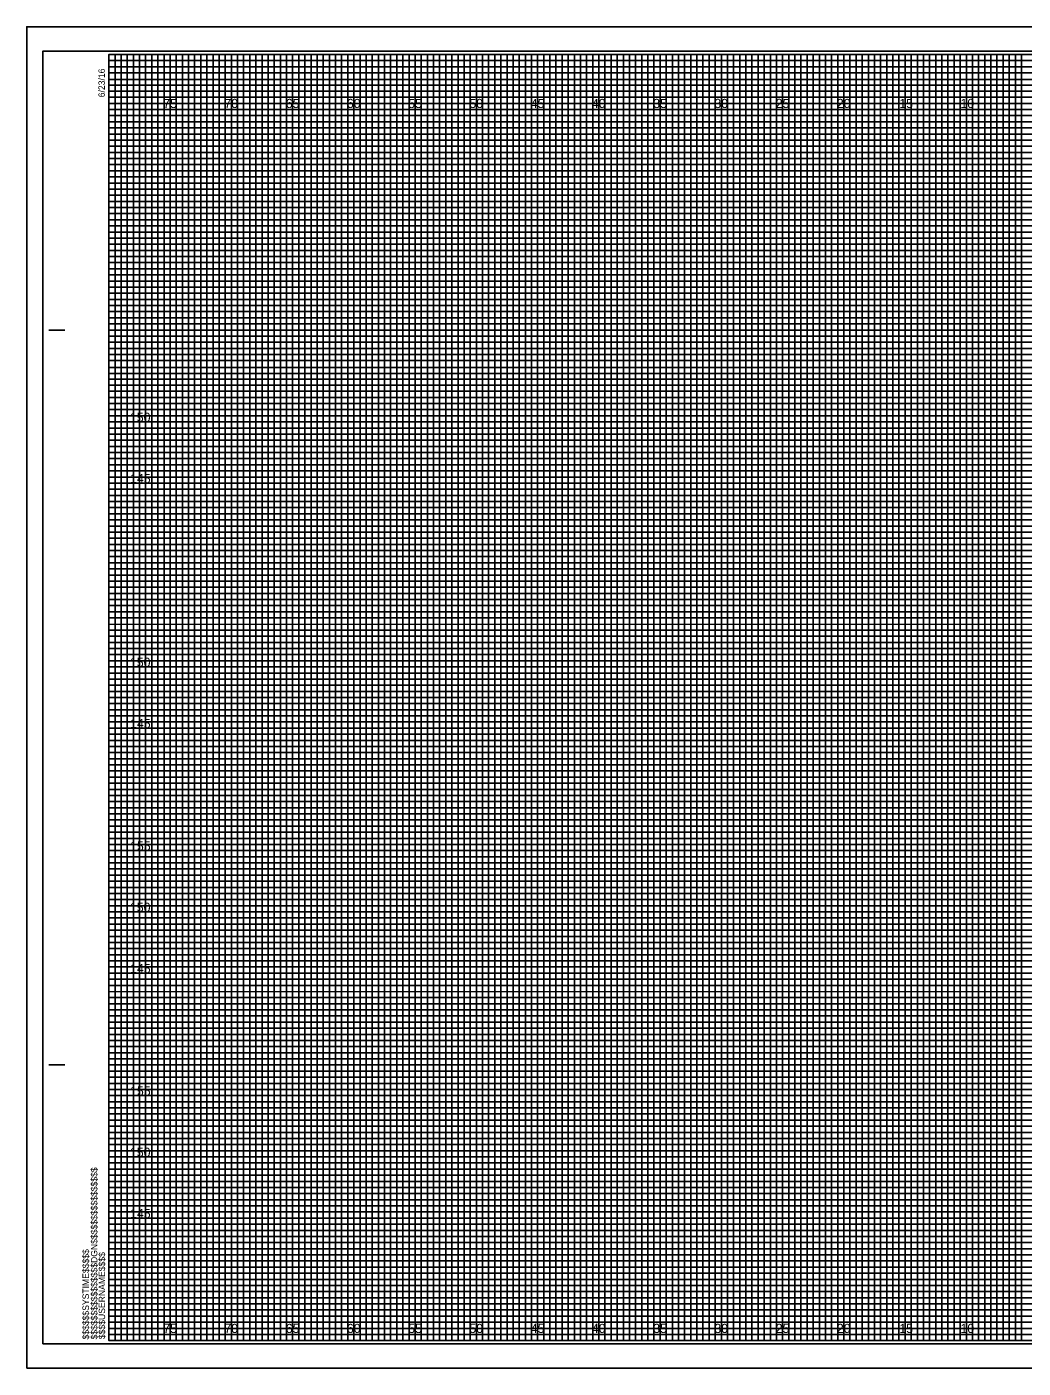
# Model space of a CAD drawing. Extents: x -7 to 162, y 218 to 327.
# Drawn here: x -6.7 to 74.6, y 217.7 to 327.2 of the extents above; entities that cross this region are included whole.
import ezdxf

# ---------------------------------------------------------------- set-up
doc = ezdxf.new("R2010")
doc.units = 0
for name, color, linetype in [('Prop CMT Conc Surface', 7, 'Continuous'), ('Prop CMT Pvmt Course 1', 7, 'Continuous'), ('Prop CMT Pvmt Course 1 CG', 7, 'Continuous'), ('Prop CMT Pvmt Surface Shoulder', 7, 'Continuous'), ('Prop CMT Pvmt Wedge Surface 1', 7, 'Continuous'), ('Prop CMT Pvmt Wedge Surface 2', 7, 'Continuous'), ('Prop CMT Pvmt Wedge Surface 3', 7, 'Continuous'), ('Prop XS Ditch Standard Text', 7, 'Continuous'), ('Prop XS Hydro Elevations', 7, 'Continuous'), ('Prop XS SE Text', 7, 'Continuous'), ('Prop XS Side Slope Text', 7, 'Continuous')]:
    doc.layers.add(name, color=color, linetype=linetype)

msp = doc.modelspace()

# ---------------------------------------------------------------- linework, layer by layer
at = {"layer": 'Prop CMT Conc Surface'}
for points in [[(0, 220), (0.5, 220), (0.5, 325), (1, 325), (1, 220)], [(1, 220), (1.5, 220), (1.5, 325), (2, 325), (2, 220)], [(2.5, 220), (3, 220), (3, 325), (3.5, 325), (3.5, 220)], [(3.5, 220), (4, 220), (4, 325), (4.5, 325), (4.5, 220)], [(5, 220), (5.5, 220), (5.5, 325), (6, 325), (6, 220)], [(6, 220), (6.5, 220), (6.5, 325), (7, 325), (7, 220)], [(7.5, 220), (8, 220), (8, 325), (8.5, 325), (8.5, 220)], [(8.5, 220), (9, 220), (9, 325), (9.5, 325), (9.5, 220)], [(10, 220), (10.5, 220), (10.5, 325), (11, 325), (11, 220)], [(11, 220), (11.5, 220), (11.5, 325), (12, 325), (12, 220)], [(12.5, 220), (13, 220), (13, 325), (13.5, 325), (13.5, 220)], [(13.5, 220), (14, 220), (14, 325), (14.5, 325), (14.5, 220)], [(15, 220), (15.5, 220), (15.5, 325), (16, 325), (16, 220)], [(16, 220), (16.5, 220), (16.5, 325), (17, 325), (17, 220)], [(17.5, 220), (18, 220), (18, 325), (18.5, 325), (18.5, 220)], [(18.5, 220), (19, 220), (19, 325), (19.5, 325), (19.5, 220)], [(20, 220), (20.5, 220), (20.5, 325), (21, 325), (21, 220)], [(21, 220), (21.5, 220), (21.5, 325), (22, 325), (22, 220)], [(22.5, 220), (23, 220), (23, 325), (23.5, 325), (23.5, 220)], [(23.5, 220), (24, 220), (24, 325), (24.5, 325), (24.5, 220)], [(25, 220), (25.5, 220), (25.5, 325), (26, 325), (26, 220)], [(26, 220), (26.5, 220), (26.5, 325), (27, 325), (27, 220)], [(27.5, 220), (28, 220), (28, 325), (28.5, 325), (28.5, 220)], [(28.5, 220), (29, 220), (29, 325), (29.5, 325), (29.5, 220)], [(30, 220), (30.5, 220), (30.5, 325), (31, 325), (31, 220)], [(31, 220), (31.5, 220), (31.5, 325), (32, 325), (32, 220)], [(32.5, 220), (33, 220), (33, 325), (33.5, 325), (33.5, 220)], [(33.5, 220), (34, 220), (34, 325), (34.5, 325), (34.5, 220)], [(35, 220), (35.5, 220), (35.5, 325), (36, 325), (36, 220)], [(36, 220), (36.5, 220), (36.5, 325), (37, 325), (37, 220)], [(37.5, 220), (38, 220), (38, 325), (38.5, 325), (38.5, 220)], [(38.5, 220), (39, 220), (39, 325), (39.5, 325), (39.5, 220)], [(40, 220), (40.5, 220), (40.5, 325), (41, 325), (41, 220)], [(41, 220), (41.5, 220), (41.5, 325), (42, 325), (42, 220)], [(42.5, 220), (43, 220), (43, 325), (43.5, 325), (43.5, 220)], [(43.5, 220), (44, 220), (44, 325), (44.5, 325), (44.5, 220)], [(45, 220), (45.5, 220), (45.5, 325), (46, 325), (46, 220)], [(46, 220), (46.5, 220), (46.5, 325), (47, 325), (47, 220)], [(47.5, 220), (48, 220), (48, 325), (48.5, 325), (48.5, 220)], [(48.5, 220), (49, 220), (49, 325), (49.5, 325), (49.5, 220)], [(50, 220), (50.5, 220), (50.5, 325), (51, 325), (51, 220)], [(51, 220), (51.5, 220), (51.5, 325), (52, 325), (52, 220)], [(52.5, 220), (53, 220), (53, 325), (53.5, 325), (53.5, 220)], [(53.5, 220), (54, 220), (54, 325), (54.5, 325), (54.5, 220)], [(55, 220), (55.5, 220), (55.5, 325), (56, 325), (56, 220)], [(56, 220), (56.5, 220), (56.5, 325), (57, 325), (57, 220)], [(57.5, 220), (58, 220), (58, 325), (58.5, 325), (58.5, 220)], [(58.5, 220), (59, 220), (59, 325), (59.5, 325), (59.5, 220)], [(60, 220), (60.5, 220), (60.5, 325), (61, 325), (61, 220)], [(61, 220), (61.5, 220), (61.5, 325), (62, 325), (62, 220)], [(62.5, 220), (63, 220), (63, 325), (63.5, 325), (63.5, 220)], [(63.5, 220), (64, 220), (64, 325), (64.5, 325), (64.5, 220)], [(65, 220), (65.5, 220), (65.5, 325), (66, 325), (66, 220)], [(66, 220), (66.5, 220), (66.5, 325), (67, 325), (67, 220)], [(67.5, 220), (68, 220), (68, 325), (68.5, 325), (68.5, 220)], [(68.5, 220), (69, 220), (69, 325), (69.5, 325), (69.5, 220)], [(70, 220), (70.5, 220), (70.5, 325), (71, 325), (71, 220)], [(71, 220), (71.5, 220), (71.5, 325), (72, 325), (72, 220)], [(72.5, 220), (73, 220), (73, 325), (73.5, 325), (73.5, 220)], [(73.5, 220), (74, 220), (74, 325), (74.5, 325), (74.5, 220)]]:
    msp.add_lwpolyline(points, dxfattribs=at)
at = {"layer": 'Prop CMT Pvmt Course 1'}
for p, q in [((-4.9, 302.5), (-3.65, 302.5)), ((-4.85, 302.5), (-3.6, 302.5)), ((-4.9, 242.5), (-3.65, 242.5)), ((-4.85, 242.5), (-3.6, 242.5)), ((0, 220), (0, 220)), ((0, 220), (0, 220)), ((0, 220), (0, 220)), ((0, 220), (0, 220)), ((0, 220), (0, 220)), ((0, 220), (0, 220)), ((0, 220), (0, 220))]:
    msp.add_line(p, q, dxfattribs=at)
msp.add_lwpolyline([(160, 325), (0, 325), (0, 220), (160, 220)], close=True, dxfattribs=at)
at = {"layer": 'Prop CMT Pvmt Course 1 CG'}
msp.add_lwpolyline([(-6.7, 217.75), (161.65, 217.75), (161.65, 327.25), (-6.7, 327.25)], close=True, dxfattribs=at)
at = {"layer": 'Prop CMT Pvmt Surface Shoulder'}
for p, q in [((0, 324.5), (130, 324.5)), ((130, 323.99), (0, 323.99)), ((0, 323.99), (0, 323.5)), ((0, 323.5), (130, 323.5)), ((130, 322.94), (0, 322.94)), ((0, 322.94), (0, 322)), ((0, 322), (160, 322))]:
    msp.add_line(p, q, dxfattribs=at)
for points in [[(0, 321.5), (135, 321.5), (160, 321.5), (160, 321), (0, 321)], [(0, 320.5), (160, 320.5), (160, 319.5), (0, 319.5)], [(0, 319), (160, 319), (160, 318.5), (0, 318.49)], [(0, 318), (160, 318), (160, 317), (0, 317)], [(0, 316.5), (160, 316.5), (160, 316), (0, 316)], [(0, 315.5), (160, 315.5), (160, 314.5), (0, 314.5)], [(0, 314), (160, 314), (160, 313.5), (0, 313.5)], [(0, 313), (160, 313), (160, 312), (0, 312)], [(0, 311.5), (160, 311.5), (160, 311), (0, 311)], [(0, 310.5), (160, 310.5), (160, 309.5), (0, 309.5)], [(0, 309), (160, 309), (160, 308.5), (0, 308.5)], [(0, 308), (160, 308), (160, 306.98), (160, 306.5), (160, 306), (0, 306)], [(0, 307), (160, 307), (160, 306.5), (0, 306.5)], [(0, 305.5), (160, 305.5), (160, 304.5), (0, 304.51)], [(0, 304.51), (160, 304.5), (160, 304), (0, 304)], [(0, 303.5), (160, 303.5), (160, 303), (0, 303)], [(0, 302), (160, 302), (160, 301.5), (0, 301.5)], [(0, 301), (160, 301), (160, 300.5), (0, 300.5)], [(-0.04, 299.44), (160, 299.44), (160, 298.94), (-0.04, 298.94)], [(0, 298.5), (160, 298.5), (160, 298), (0, 298)], [(0, 297), (160, 297), (160, 296.5), (0, 296.5)], [(0, 296), (160, 296), (160, 295.5), (0, 295.5)], [(0, 294.5), (160, 294.5), (160, 294), (0, 294)], [(0, 293.5), (160, 293.5), (160, 293), (0, 293)], [(0, 292), (160, 292), (160, 291.5), (0, 291.5)], [(0, 291), (160, 291), (160, 290.5), (0, 290.5)], [(0, 289.5), (160, 289.5), (160, 288.99), (0, 289)], [(0, 288.5), (160, 288.5), (160, 288), (0, 288)], [(0, 287), (160, 287), (160, 286.5), (0, 286.5)], [(0, 286), (160, 286), (160, 285.5), (0, 285.5)], [(0, 284.5), (160, 284.5), (160, 284), (0, 284)], [(0, 283.5), (160, 283.5), (160, 283), (0, 283)], [(0, 282), (160, 282), (160, 281.5), (0, 281.5)], [(0, 281), (160, 281), (160, 280.5), (0, 280.5)], [(0, 279.5), (160, 279.5), (160, 279), (0, 279)], [(0, 278.5), (160.03, 278.45), (160, 278), (0, 278)], [(0, 277), (160, 277), (160, 276.5), (0, 276.5)], [(0, 276), (160, 276), (160, 275.5), (0, 275.5)], [(0, 274.5), (160, 274.5), (160, 274), (0, 274)], [(0, 273.5), (160, 273.5), (160, 273), (0, 273)], [(0, 272), (160, 272), (160, 271.5), (0, 271.5)], [(0, 271), (160, 271), (160, 270.5), (0, 270.5)], [(0, 269.5), (160, 269.5), (160, 269), (0, 269)], [(0, 268.5), (160, 268.5), (160, 268), (0, 268)], [(0, 267), (160, 267), (160, 266.5), (0, 266.5)], [(0, 266), (160, 266), (160, 265.5), (0, 265.5)], [(0, 264.5), (160, 264.5), (160, 264), (0, 264)], [(0, 263.5), (160, 263.5), (160, 263), (0, 263)], [(0, 262), (160, 262), (160, 261.5), (0, 261.5)], [(0, 261), (160, 261), (160, 260.5), (0, 260.5)], [(0, 259.5), (160, 259.5), (160, 258.99), (0, 259)], [(0, 258.5), (160, 258.5), (160, 258), (0, 258)], [(0, 257), (160, 257), (160, 256.5), (0, 256.5)], [(0, 256), (160, 256), (160, 255.5), (0, 255.5)], [(0, 254.5), (160, 254.5), (160, 254), (0, 254)], [(0, 253.5), (160, 253.5), (160, 253), (0, 253)], [(0, 252), (160, 252), (160, 251.5), (0, 251.5)], [(0, 251), (160, 251), (160, 250.5), (0, 250.5)], [(0, 249.5), (160, 249.5), (160, 249), (0, 249)], [(0, 248.5), (160.03, 248.46), (160, 248), (0, 248)], [(0, 247), (160, 247), (160, 246.5), (0, 246.5)], [(0, 246), (160, 246), (160, 245.5), (0, 245.5)], [(0, 244.5), (160, 244.5), (160, 244), (0, 244)], [(0, 243.5), (160, 243.5), (160, 243), (0, 243)], [(0, 242), (160, 242), (160, 241.5), (0, 241.5)], [(0, 241), (160, 241), (160, 240.5), (0, 240.5)], [(0, 239.5), (160, 239.5), (160, 239), (0, 239)], [(0, 238.5), (160, 238.5), (160, 238), (0, 238)], [(0, 237), (160, 237), (160, 236.5), (0, 236.5)], [(0, 236), (160, 236), (160, 235.5), (0, 235.5)], [(0, 234.5), (160, 234.5), (160, 234), (0, 234)], [(0, 233.5), (160, 233.5), (160, 233), (0, 233)], [(0, 232), (160, 232), (160, 231.5), (0, 231.5)], [(0, 231), (160, 231), (160, 230.5), (0, 230.5)], [(0, 229.5), (160, 229.5), (160, 229), (0, 229)], [(0, 228.5), (160, 228.5), (160, 228), (0, 228)], [(0, 227), (160, 227), (160, 226.5), (0, 226.5)], [(0, 226), (160, 226), (160, 225.5), (0, 225.5)], [(0, 224.5), (160, 224.5), (160, 224), (0, 224)], [(0, 223.5), (160, 223.5), (160, 223), (0, 223)], [(0, 222), (160, 222), (160, 221.5), (0, 221.5)], [(0, 221), (160, 221), (160, 220.5), (0, 220.5)]]:
    msp.add_lwpolyline(points, dxfattribs=at)
at = {"layer": 'Prop CMT Pvmt Wedge Surface 2'}
for p, q in [((5, 325), (0, 325)), ((5, 220), (5, 325)), ((15, 325), (10, 325)), ((10, 325), (10, 220)), ((15, 220), (15, 325)), ((25, 325), (20, 325)), ((20, 325), (20, 220)), ((25, 220), (25, 325)), ((35, 325), (30, 325)), ((30, 325), (30, 220)), ((35, 220), (35, 325)), ((45, 325), (40, 325)), ((40, 325), (40, 220)), ((45, 220), (45, 325)), ((55, 325), (50, 325)), ((50, 325), (50, 220)), ((55, 220), (55, 325)), ((65, 325), (60, 325)), ((60, 325), (60, 220)), ((65, 220), (65, 325)), ((75, 325), (70, 325)), ((70, 325), (70, 220)), ((10, 220), (5, 220)), ((20, 220), (15, 220)), ((30, 220), (25, 220)), ((40, 220), (35, 220)), ((50, 220), (45, 220)), ((60, 220), (55, 220)), ((70, 220), (65, 220))]:
    msp.add_line(p, q, dxfattribs=at)
for points in [[(0, 320), (160, 320), (160, 315), (0, 315)], [(0, 310), (160, 310), (160, 305), (0, 305)], [(0, 300), (160, 300), (160, 295), (0, 295)], [(0, 290), (160, 290), (160, 285), (0, 285)], [(0, 280), (160, 280), (160, 275), (0, 275)], [(0, 270), (160, 270), (160, 265), (0, 265)], [(0, 260), (160, 260), (160, 255), (0, 255)], [(0, 250), (160, 250), (160, 245), (0, 245)], [(0, 240), (160, 240), (160, 235), (0, 235)], [(0, 230), (160, 230), (160, 225), (0, 225)]]:
    msp.add_lwpolyline(points, dxfattribs=at)
at = {"layer": 'Prop CMT Pvmt Wedge Surface 3'}
for points in [[(0, 325), (2.5, 325), (2.5, 220), (7.5, 220), (7.5, 325), (12.5, 325), (12.5, 220), (17.5, 220), (17.5, 325), (22.5, 325), (22.5, 220), (27.5, 220), (27.5, 325), (32.5, 325), (32.5, 220), (37.5, 220), (37.5, 325), (42.5, 325), (42.5, 220), (47.5, 220), (47.5, 325), (52.5, 325), (52.5, 220), (57.5, 220), (57.5, 325), (62.5, 325), (62.5, 220), (67.5, 220), (67.5, 325), (72.5, 325), (72.5, 220), (77.5, 220)], [(0, 322.5), (137.5, 322.5)], [(0, 312.5), (160, 312.5), (160, 317.5), (0, 317.5)], [(0, 302.5), (160, 302.5), (160, 307.5), (0, 307.5)], [(0, 292.5), (160, 292.5), (160, 297.5), (0, 297.5)], [(0, 282.5), (160, 282.5), (160, 287.5), (0, 287.5)], [(0, 272.5), (160, 272.5), (160, 277.5), (0, 277.5)], [(0, 262.5), (160, 262.5), (160, 267.5), (0, 267.5)], [(0, 252.5), (160, 252.5), (160, 257.5), (0, 257.5)], [(0, 242.5), (160, 242.5), (160, 247.5), (0, 247.5)], [(0, 232.5), (160, 232.5), (160, 237.5), (0, 237.5)], [(0, 222.5), (160, 222.5), (160, 227.5), (0, 227.5)]]:
    msp.add_lwpolyline(points, dxfattribs=at)
at = {"layer": 'Prop XS Ditch Standard Text'}
for p, q in [((161.65, 327.25), (-6.7, 327.25)), ((-6.7, 327.25), (-6.7, 217.75)), ((-6.7, 217.75), (161.65, 217.75))]:
    msp.add_line(p, q, dxfattribs=at)
at = {"layer": 'Prop XS SE Text'}
for p, q in [((5, 220), (5, 325)), ((10, 220), (10, 325)), ((15, 220), (15, 325)), ((20, 220), (20, 325)), ((25, 220), (25, 325)), ((30, 220), (30, 325)), ((35, 220), (35, 325)), ((40, 220), (40, 325)), ((45, 220), (45, 325)), ((50, 220), (50, 325)), ((55, 220), (55, 325)), ((60, 220), (60, 325)), ((65, 220), (65, 325)), ((70, 220), (70, 325)), ((0, 320), (160, 320)), ((0, 315), (160, 315)), ((0, 310), (160, 310)), ((0, 305), (160, 305)), ((0, 300), (160, 300)), ((0, 295), (160, 295)), ((0, 290), (160, 290)), ((0, 285), (160, 285)), ((0, 280), (160, 280)), ((0, 275), (160, 275)), ((0, 270), (160, 270)), ((0, 265), (160, 265)), ((0, 260), (160, 260)), ((0, 255), (160, 255)), ((0, 250), (160, 250)), ((0, 245), (160, 245)), ((0, 240), (160, 240)), ((0, 235), (160, 235)), ((0, 230), (160, 230)), ((0, 225), (160, 225))]:
    msp.add_line(p, q, dxfattribs=at)
at = {"layer": 'Prop XS Side Slope Text'}
msp.add_lwpolyline([(-5.4, 219.75), (161.2, 219.75), (161.2, 325.25), (-5.4, 325.25)], close=True, dxfattribs=at)

# ---------------------------------------------------------------- texts
at = {"layer": 'Prop CMT Pvmt Course 1'}
for s, p in [('6/23/16', (-0.33, 321.5)), ('$$$$$$$$$$$$$$$$DGN$$$$$$$$$$$$$$$$', (-0.94, 220.09)), ('$$$$$$SYSTIME$$$$$', (-1.63, 220.09)), ('$$$$USERNAME$$$$', (-0.31, 220.12))]:
    msp.add_text(s, height=0.525, rotation=90, dxfattribs=at).set_placement(p)
at = {"layer": 'Prop CMT Pvmt Wedge Surface 1'}
for s, p in [('75', (4.44, 320.62)), ('70', (9.43, 320.62)), ('65', (14.44, 320.62)), ('60', (19.43, 320.62)), ('55', (24.44, 320.62)), ('50', (29.43, 320.62)), ('45', (34.44, 320.62)), ('40', (39.43, 320.62)), ('35', (44.44, 320.62)), ('30', (49.43, 320.62)), ('25', (54.44, 320.62)), ('20', (59.43, 320.62)), ('15', (64.53, 320.62)), ('10', (69.52, 320.62)), ('75', (4.44, 220.62)), ('70', (9.43, 220.62)), ('65', (14.44, 220.62)), ('60', (19.43, 220.62)), ('55', (24.44, 220.62)), ('50', (29.43, 220.62)), ('45', (34.44, 220.62)), ('40', (39.43, 220.62)), ('35', (44.44, 220.62)), ('30', (49.43, 220.62)), ('25', (54.44, 220.62)), ('20', (59.43, 220.62)), ('15', (64.53, 220.62)), ('10', (69.52, 220.62))]:
    msp.add_text(s, height=0.75, dxfattribs=at).set_placement(p)
at = {"layer": 'Prop XS Hydro Elevations'}
for s, p in [('150', (1.72, 295)), ('145', (1.73, 290)), ('150', (1.72, 275)), ('145', (1.73, 270)), ('155', (1.73, 260)), ('150', (1.72, 255)), ('145', (1.73, 250)), ('155', (1.73, 240)), ('150', (1.72, 235)), ('145', (1.73, 230))]:
    msp.add_text(s, height=0.75, dxfattribs=at).set_placement(p)

doc.saveas('drawing.dxf')
